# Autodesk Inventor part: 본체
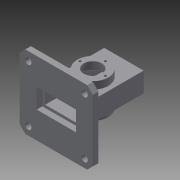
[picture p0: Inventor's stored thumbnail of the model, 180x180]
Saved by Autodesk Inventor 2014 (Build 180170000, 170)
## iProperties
Created: 2016-02
Part Number: 본체
Material: Generic
Document SubType Name: Modeling
Designer: user
Density: 1 g/cm^3
Appearance: Default
Author: user
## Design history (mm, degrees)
sketch "Sketch1"
  geometry: L1 (-34.681, 55)-(35.319, 55); L2 (35.319, 55)-(35.319, -55); L3 (35.319, -55)-(-34.681, -55); L4 (-34.681, -55)-(-34.681, 55); 1 further point
  constraints: 8 end point, 2 parallel, 1 horizontal, 1 perpendicular
  dimensions: "d0" = 70 distance of L1.start L1.end; "d1" = 110 distance of L1.end L2.end
extrude "Extrusion1" new body sketch "Sketch1" stored distance "d4" = 35; taper "d5" = 0 deg
sketch "Sketch2"
  geometry: C1 r 27.5 at (0, 0); 1 further point
  constraints: 1 centre point, 1 coincident
  dimensions: "d6" = 55 diameter of C1
extrude "Extrusion2" join sketch "Sketch2" distance "d7" = 13; taper "d8" = 0 deg
shell "Shell1" dims "d9" = 5
sketch "Sketch3"
  geometry: 4 further points
hole "Hole1" sketch "Sketch3" at (0, 22.5), (-22.5, 0), (0, -22.5), (22.5, 0) diameter "d11" = 4; stored, may be unused: countersink angle "d15" = 90 deg, drill point angle "d17" = 118 deg; dims "d12" = 6, "d13" = 9.4, "d14" = 4.775, "d16" = 8
sketch "Sketch4"
  geometry: C1 r 27.5 at (0, 0) reference; C2 r 16 at (0, 0)
  constraints: 1 centre point, 1 coincident
  dimensions: "d18" = 32 diameter of C2
extrude "Extrusion3" cut sketch "Sketch4" stored distance "d19" = 13; taper "d20" = 0 deg
sketch "Sketch5"
  geometry: C1 r 22.5 at (30.319, -50) reference; C2 r 27.5 at (30.319, -50)
  constraints: 1 centre point, 1 coincident
  dimensions: "d21" = 55 diameter of C2
extrude "Extrusion4" join sketch "Sketch5" distance "d22" = 7; taper "d23" = -45 deg
mirror "Mirror1"
sketch "Sketch6"
  geometry: L1 (70, 0)-(70, -35) reference; L2 (0, 0)-(70, 0) reference; L3 (0, 0)-(0, -35) reference; L4 (70, -35)-(0, -35) reference; L5 (-30.319, 47.5)-(99.681, 47.5); L6 (99.681, 47.5)-(99.681, -82.5); L7 (99.681, -82.5)-(-30.319, -82.5); L8 (-30.319, -82.5)-(-30.319, 47.5); 1 further point
  constraints: 8 end point, 2 parallel, 1 horizontal, 1 perpendicular
  dimensions: "d24" = 130 distance of L5.start L5.end; "d25" = 130 distance of L5.end L6.end; "d26" = 65 horizontal distance of L5.end point (34.681, -17.5); "d27" = 65 distance from line of L8 point (34.681, -17.5)
extrude "Extrusion5" join sketch "Sketch6" distance "d28" = 10; taper "d29" = 0 deg
sketch "Sketch7"
  geometry: L1 (-15.319, 67.5)-(84.681, 67.5); L2 (84.681, 67.5)-(84.681, -32.5); L3 (84.681, -32.5)-(-15.319, -32.5); L4 (-15.319, -32.5)-(-15.319, 67.5); 2 further points
  constraints: 8 end point, 2 parallel, 1 horizontal, 1 perpendicular
  dimensions: "d30" = 100 distance of L1.start L1.end; "d31" = 100 distance of L1.end L2.end; "d32" = 15 horizontal distance of L1.end point (99.681, 82.5); "d33" = 15 horizontal distance of point (99.681, 82.5) L1.end
hole "Hole2" sketch "Sketch7" at (84.681, 67.5), (84.681, -32.5), (-15.319, -32.5), (-15.319, 67.5) diameter "d34" = 12; stored, may be unused: countersink angle "d38" = 90 deg, drill point angle "d40" = 0 deg; dims "d35" = 6, "d36" = 9.4, "d37" = 4.775, "d39" = 8
chamfer "Chamfer1" distance "d41" = 10; stored, may be unused: second distance "d42" = 2, angle "d43" = 45 deg
body "Solid1"
